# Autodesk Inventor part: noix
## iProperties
Author: Administrateur
Shininess: 20.0
PropertySet Name: _Private Model Information
Length Units: 11269
Angle Units: 11283
Time Units: 11279
Mass Units: 11290
Length Display Precision: 3
Angle Display Precision: 2
Compacted: False
Created: 2001-04
Part Number: noix
Material: Par défaut
Document SubType Name: Modélisation
Designer: Administrateur
Control State: 0
Master: False
Checked Out: False
PropertySet Name: Design Tracking Control
Density: 0.0
Volumn: 0.0
Area: 0.0
PropertySet Name: Model Information
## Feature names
1. Extrusion12
